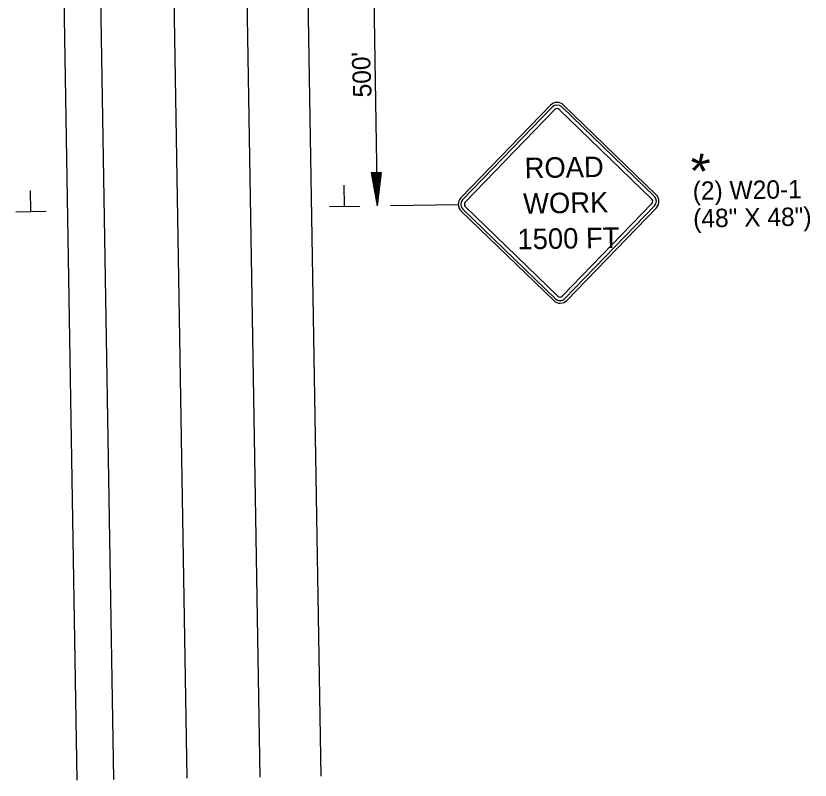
# Model space of a CAD drawing. Extents: x 1676063 to 1678026, y 228339 to 229904.
# Drawn here: x 1677075.6 to 1677335.3, y 228490 to 228739.9 of the extents above; entities that cross this region are included whole.
import ezdxf

# ---------------------------------------------------------------- set-up
doc = ezdxf.new("R2010")
doc.units = 0
for name, color, linetype in [('P_TC_Signs_Temporary', 7, 'Continuous'), ('R_Annotation', 7, 'Continuous'), ('R_Draft', 7, 'Continuous')]:
    doc.layers.add(name, color=color, linetype=linetype)

msp = doc.modelspace()

# ---------------------------------------------------------------- linework, layer by layer
at = {"layer": 'P_TC_Signs_Temporary'}
for p, q in [((1677221.08, 228680.4), (1677250.39, 228710.7)), ((1677221.68, 228679.82), (1677251, 228710.12)), ((1677254.07, 228710.17), (1677284.37, 228680.86)), ((1677254.65, 228710.77), (1677284.95, 228681.46)), ((1677222.53, 228679), (1677251.84, 228709.3)), ((1677253.26, 228709.33), (1677283.56, 228680.02)), ((1677252.03, 228647.43), (1677221.74, 228676.74)), ((1677252.85, 228648.27), (1677222.55, 228677.58)), ((1677283.58, 228678.6), (1677254.27, 228648.3)), ((1677284.42, 228677.78), (1677255.11, 228647.48)), ((1677285.02, 228677.2), (1677255.71, 228646.9)), ((1677251.45, 228646.83), (1677221.15, 228676.14))]:
    msp.add_line(p, q, dxfattribs=at)
for centre, radius, start, end in [((1677252.56, 228708.61), 3.01, 45.9497, 135.9497), ((1677252.56, 228708.61), 2.17, 45.9497, 135.9497), ((1677252.56, 228708.61), 1, 45.9497, 135.9497), ((1677223.25, 228678.31), 3.01, 135.9497, 225.9497), ((1677223.25, 228678.31), 2.17, 135.9497, 225.9497), ((1677223.25, 228678.31), 1, 135.9497, 225.9497), ((1677282.86, 228679.29), 1, 315.9497, 45.9497), ((1677282.86, 228679.29), 2.17, 315.9497, 45.9497), ((1677282.86, 228679.29), 3.01, 315.9497, 45.9497), ((1677253.55, 228648.99), 1, 225.9497, 315.9497), ((1677253.55, 228648.99), 3.01, 225.9497, 315.9497), ((1677253.55, 228648.99), 2.17, 225.9497, 315.9497)]:
    msp.add_arc(centre, radius, start, end, dxfattribs=at)
at = {"layer": 'R_Draft'}
for p, q in [((1677095.67, 228490.01), (1677088.48, 228923.95)), ((1677107.64, 228490.2), (1677100.45, 228924.15)), ((1677131.58, 228490.6), (1677124.38, 228924.55)), ((1677155.51, 228491), (1677148.32, 228924.95)), ((1677175.46, 228491.33), (1677168.26, 228925.28)), ((1677192.07, 228777.8), (1677193.75, 228677.94)), ((1677195, 228688.74), (1677191.73, 228688.64)), ((1677191.73, 228688.64), (1677193.72, 228677.82)), ((1677192.01, 228688.65), (1677193.66, 228679.63)), ((1677192.29, 228688.66), (1677193.6, 228681.5)), ((1677192.56, 228688.67), (1677193.54, 228683.31)), ((1677192.84, 228688.68), (1677193.48, 228685.16)), ((1677193.11, 228688.68), (1677193.42, 228686.98)), ((1677193.62, 228688.7), (1677193.42, 228686.98)), ((1677193.9, 228688.71), (1677193.48, 228685.16)), ((1677194.18, 228688.72), (1677193.54, 228683.31)), ((1677194.45, 228688.72), (1677193.6, 228681.5)), ((1677194.73, 228688.73), (1677193.66, 228679.63)), ((1677195, 228688.74), (1677193.72, 228677.82)), ((1677183.11, 228677.78), (1677183, 228684.54)), ((1677080.56, 228676.08), (1677080.45, 228682.84)), ((1677178.19, 228677.56), (1677188.09, 228677.72)), ((1677198.11, 228677.89), (1677220.24, 228678.26)), ((1677075.64, 228675.86), (1677085.54, 228676.02))]:
    msp.add_line(p, q, dxfattribs=at)

# ---------------------------------------------------------------- texts
at = {"layer": 'P_TC_Signs_Temporary'}
for s, p in [(' ROAD ', (1677239.52, 228686.8)), ('WORK', (1677241.52, 228675.21)), ('1500 FT', (1677239.66, 228663.56))]:
    msp.add_text(s, height=6.692, rotation=0.9497, dxfattribs=at).set_placement(p)
at = {"layer": 'R_Annotation'}
for s, height, rotation, p in [("500'", 6, 92.1801, (1677191.94, 228713.38)), ('*', 12, 135.9497, (1677307.7, 228695.99)), ('(2) W20-1', 6, 0.9497, (1677296.95, 228679.72)), ('(48" X 48")', 6, 0.9497, (1677297.1, 228670.72))]:
    msp.add_text(s, height=height, rotation=rotation, dxfattribs=at).set_placement(p)

doc.saveas('drawing.dxf')
